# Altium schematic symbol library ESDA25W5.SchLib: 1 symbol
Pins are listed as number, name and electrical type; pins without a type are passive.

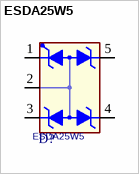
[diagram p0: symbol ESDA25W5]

## ESDA25W5
designator D?
footprint ST_SOT323-5L
pins: 1, 2, 3, 4, 5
